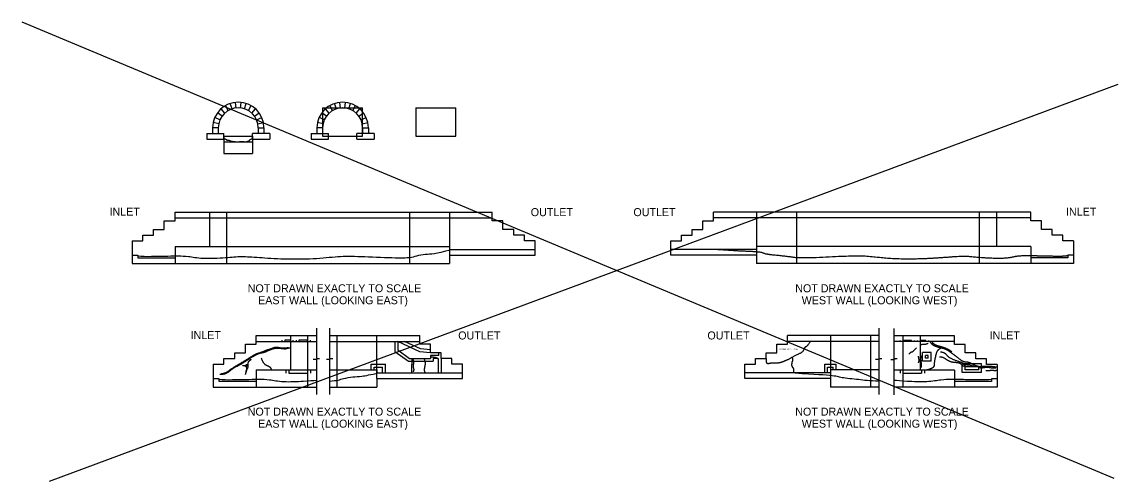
# Model space of a CAD drawing. Extents: x 21249 to 21441, y 6062 to 6293.
# Drawn here: x 21249.2 to 21441, y 6212.1 to 6292.5 of the extents above; entities that cross this region are included whole.
import ezdxf

# ---------------------------------------------------------------- set-up
doc = ezdxf.new("R2010")
doc.units = 0
for name, color, linetype in [('BR_P_Slab_Hidden', 7, 'Continuous'), ('BR_P_Slab_Object', 7, 'Continuous'), ('DR_X_Culvert', 7, 'Continuous'), ('SC_Scratch1', 7, 'Continuous'), ('SC_Scratch2', 7, 'Continuous'), ('SH_Text', 7, 'Continuous'), ('XS_X_Ground_Line', 7, 'Continuous')]:
    doc.layers.add(name, color=color, linetype=linetype)

msp = doc.modelspace()

# ---------------------------------------------------------------- linework, layer by layer
at = {"layer": 'BR_P_Slab_Hidden'}
msp.add_line((21284.56, 6271.49), (21289.56, 6271.49), dxfattribs=at)
at = {"layer": 'BR_P_Slab_Object'}
for p, q in [((21284.56, 6272.49), (21289.56, 6272.49)), ((21284.56, 6272.49), (21284.56, 6269.49)), ((21289.56, 6272.49), (21289.56, 6269.49)), ((21284.56, 6269.49), (21289.56, 6269.49))]:
    msp.add_line(p, q, dxfattribs=at)
at = {"layer": 'DR_X_Culvert'}
for p, q in [((21285.97, 6277.28), (21285.66, 6278.23)), ((21286.69, 6277.44), (21286.58, 6278.43)), ((21287.43, 6277.44), (21287.54, 6278.43)), ((21288.15, 6277.28), (21288.46, 6278.23)), ((21304.23, 6277.28), (21303.92, 6278.23)), ((21304.95, 6277.44), (21304.84, 6278.43)), ((21305.7, 6277.44), (21305.8, 6278.43)), ((21306.41, 6277.28), (21306.72, 6278.23)), ((21284.22, 6276.01), (21283.41, 6276.59)), ((21284.71, 6276.55), (21284.04, 6277.3)), ((21285.3, 6276.99), (21284.8, 6277.85)), ((21288.82, 6276.99), (21289.32, 6277.85)), ((21289.41, 6276.55), (21290.08, 6277.3)), ((21289.9, 6276.01), (21290.71, 6276.59)), ((21302.48, 6276.01), (21301.67, 6276.59)), ((21301.82, 6277.49), (21308.82, 6277.49)), ((21301.82, 6277.49), (21301.82, 6272.49)), ((21302.97, 6276.55), (21302.3, 6277.3)), ((21303.56, 6276.99), (21303.06, 6277.85)), ((21307.08, 6276.99), (21307.58, 6277.85)), ((21307.67, 6276.55), (21308.34, 6277.3)), ((21308.16, 6276.01), (21308.97, 6276.59)), ((21308.82, 6272.49), (21308.82, 6277.49)), ((21318.12, 6277.49), (21318.12, 6272.49)), ((21318.12, 6277.49), (21325.12, 6277.49)), ((21325.12, 6272.49), (21325.12, 6277.49)), ((21283.63, 6274.68), (21282.66, 6274.88)), ((21283.86, 6275.37), (21282.94, 6275.78)), ((21290.26, 6275.37), (21291.18, 6275.78)), ((21290.49, 6274.68), (21291.46, 6274.88)), ((21301.9, 6274.68), (21300.92, 6274.88)), ((21302.12, 6275.37), (21301.21, 6275.78)), ((21308.52, 6275.37), (21309.44, 6275.78)), ((21308.75, 6274.68), (21309.72, 6274.88)), ((21281.56, 6272.99), (21284.56, 6272.99)), ((21281.56, 6272.99), (21281.56, 6271.99)), ((21283.56, 6273.99), (21282.56, 6273.99)), ((21282.56, 6273.99), (21282.56, 6272.99)), ((21283.56, 6273.99), (21283.56, 6272.99)), ((21284.56, 6271.99), (21284.56, 6272.99)), ((21292.56, 6272.99), (21289.56, 6272.99)), ((21289.56, 6271.99), (21289.56, 6272.99)), ((21290.56, 6273.99), (21290.56, 6272.99)), ((21290.56, 6273.99), (21291.56, 6273.99)), ((21291.56, 6273.99), (21291.56, 6272.99)), ((21292.56, 6272.99), (21292.56, 6271.99)), ((21299.82, 6272.99), (21302.82, 6272.99)), ((21299.82, 6272.99), (21299.82, 6271.99)), ((21301.82, 6273.99), (21300.82, 6273.99)), ((21300.82, 6273.99), (21300.82, 6272.99)), ((21301.82, 6273.99), (21301.82, 6272.99)), ((21301.82, 6272.49), (21308.82, 6272.49)), ((21302.82, 6271.99), (21302.82, 6272.99)), ((21310.82, 6272.99), (21307.82, 6272.99)), ((21307.82, 6271.99), (21307.82, 6272.99)), ((21308.82, 6273.99), (21308.82, 6272.99)), ((21308.82, 6273.99), (21309.82, 6273.99)), ((21309.82, 6273.99), (21309.82, 6272.99)), ((21310.82, 6272.99), (21310.82, 6271.99)), ((21318.12, 6272.49), (21325.12, 6272.49)), ((21281.56, 6271.99), (21284.56, 6271.99)), ((21289.56, 6271.99), (21292.56, 6271.99)), ((21299.82, 6271.99), (21302.82, 6271.99)), ((21307.82, 6271.99), (21310.82, 6271.99)), ((21276, 6259.19), (21331.5, 6259.19)), ((21276, 6257.69), (21276, 6259.19)), ((21282, 6259.19), (21282, 6253.19)), ((21285, 6259.19), (21285, 6250.19)), ((21285, 6259.19), (21285, 6250.19)), ((21317, 6259.19), (21317, 6250.19)), ((21324, 6259.19), (21324, 6250.19)), ((21324, 6259.19), (21324, 6251.69)), ((21331.5, 6257.69), (21331.5, 6259.19)), ((21425.73, 6259.19), (21370.23, 6259.19)), ((21370.23, 6257.69), (21370.23, 6259.19)), ((21377.73, 6259.19), (21377.73, 6251.69)), ((21384.73, 6259.19), (21384.73, 6250.19)), ((21416.73, 6259.19), (21416.73, 6250.19)), ((21419.73, 6259.19), (21419.73, 6253.19)), ((21425.73, 6257.69), (21425.73, 6259.19)), ((21274.12, 6256.19), (21274.12, 6257.69)), ((21274.12, 6257.69), (21276, 6257.69)), ((21276, 6258.19), (21331.5, 6258.19)), ((21333.37, 6257.69), (21331.5, 6257.69)), ((21333.37, 6256.19), (21333.37, 6257.69)), ((21368.36, 6256.19), (21368.36, 6257.69)), ((21368.36, 6257.69), (21370.23, 6257.69)), ((21425.73, 6258.19), (21370.23, 6258.19)), ((21427.61, 6257.69), (21425.73, 6257.69)), ((21427.61, 6256.19), (21427.61, 6257.69)), ((21270.37, 6254.19), (21270.37, 6255.19)), ((21270.37, 6255.19), (21272.25, 6255.19)), ((21272.25, 6255.19), (21272.25, 6256.19)), ((21272.25, 6256.19), (21274.12, 6256.19)), ((21335.25, 6256.19), (21333.37, 6256.19)), ((21335.25, 6255.19), (21335.25, 6256.19)), ((21337.12, 6255.19), (21335.25, 6255.19)), ((21337.12, 6254.19), (21337.12, 6255.19)), ((21364.61, 6254.19), (21364.61, 6255.19)), ((21364.61, 6255.19), (21366.48, 6255.19)), ((21366.48, 6255.19), (21366.48, 6256.19)), ((21366.48, 6256.19), (21368.36, 6256.19)), ((21429.48, 6256.19), (21427.61, 6256.19)), ((21429.48, 6255.19), (21429.48, 6256.19)), ((21431.36, 6255.19), (21429.48, 6255.19)), ((21431.36, 6254.19), (21431.36, 6255.19)), ((21268.5, 6254.19), (21268.5, 6250.19)), ((21268.5, 6254.19), (21270.37, 6254.19)), ((21276, 6253.19), (21324, 6253.19)), ((21276, 6253.19), (21276, 6250.19)), ((21324, 6253.19), (21324, 6252.69)), ((21339, 6254.19), (21337.12, 6254.19)), ((21339, 6251.69), (21339, 6254.19)), ((21362.73, 6251.69), (21362.73, 6254.19)), ((21362.73, 6254.19), (21364.61, 6254.19)), ((21425.73, 6253.19), (21377.73, 6253.19)), ((21377.73, 6253.19), (21377.73, 6252.69)), ((21425.73, 6253.19), (21425.73, 6250.19)), ((21433.23, 6254.19), (21431.36, 6254.19)), ((21433.23, 6254.19), (21433.23, 6250.19)), ((21268.5, 6251.69), (21269.5, 6251.69)), ((21269.5, 6251.69), (21269.5, 6251.19)), ((21269.5, 6251.19), (21276, 6251.19)), ((21324, 6252.69), (21339, 6252.69)), ((21324, 6251.69), (21339, 6251.69)), ((21324, 6251.69), (21324, 6250.19)), ((21377.73, 6252.69), (21362.73, 6252.69)), ((21377.73, 6251.69), (21362.73, 6251.69)), ((21377.73, 6251.69), (21377.73, 6250.19)), ((21432.23, 6251.19), (21425.73, 6251.19)), ((21433.23, 6251.69), (21432.23, 6251.69)), ((21432.23, 6251.69), (21432.23, 6251.19)), ((21268.5, 6250.19), (21324, 6250.19)), ((21433.23, 6250.19), (21377.73, 6250.19)), ((21288.31, 6234.59), (21288.31, 6236.09)), ((21288.31, 6236.09), (21290.18, 6236.09)), ((21290.18, 6237.59), (21300.72, 6237.59)), ((21290.18, 6236.09), (21290.18, 6237.59)), ((21290.18, 6236.59), (21300.72, 6236.59)), ((21296.18, 6237.59), (21296.18, 6231.59)), ((21299.18, 6237.59), (21299.18, 6228.59)), ((21303.05, 6237.59), (21318.81, 6237.59)), ((21303.05, 6236.59), (21318.81, 6236.59)), ((21304.31, 6237.59), (21304.31, 6228.59)), ((21311.31, 6230.09), (21311.31, 6237.59)), ((21318.81, 6236.09), (21318.81, 6237.59)), ((21320.68, 6236.09), (21318.81, 6236.09)), ((21320.68, 6234.59), (21320.68, 6236.09)), ((21381.31, 6234.59), (21381.31, 6236.09)), ((21381.31, 6236.09), (21383.18, 6236.09)), ((21383.18, 6236.09), (21383.18, 6237.59)), ((21399.13, 6237.59), (21383.18, 6237.59)), ((21399.13, 6236.59), (21383.18, 6236.59)), ((21390.68, 6237.59), (21390.68, 6230.09)), ((21397.68, 6237.59), (21397.68, 6228.59)), ((21412.37, 6237.55), (21401.79, 6237.55)), ((21412.37, 6236.55), (21401.79, 6236.55)), ((21403.37, 6237.55), (21403.37, 6228.55)), ((21406.37, 6237.55), (21406.37, 6231.55)), ((21412.37, 6236.05), (21412.37, 6237.55)), ((21414.24, 6236.05), (21412.37, 6236.05)), ((21414.24, 6234.55), (21414.24, 6236.05)), ((21286.43, 6233.59), (21286.43, 6234.59)), ((21286.43, 6234.59), (21288.31, 6234.59)), ((21322.56, 6234.59), (21320.68, 6234.59)), ((21322.56, 6233.59), (21322.56, 6234.59)), ((21379.43, 6233.59), (21379.43, 6234.59)), ((21379.43, 6234.59), (21381.31, 6234.59)), ((21416.12, 6234.55), (21414.24, 6234.55)), ((21416.12, 6233.55), (21416.12, 6234.55)), ((21282.68, 6232.59), (21282.68, 6228.59)), ((21282.68, 6232.59), (21284.56, 6232.59)), ((21284.56, 6232.59), (21284.56, 6233.59)), ((21284.56, 6233.59), (21286.43, 6233.59)), ((21324.43, 6233.59), (21322.56, 6233.59)), ((21324.43, 6232.59), (21324.43, 6233.59)), ((21326.31, 6232.59), (21324.43, 6232.59)), ((21326.31, 6230.09), (21326.31, 6232.59)), ((21375.68, 6230.09), (21375.68, 6232.59)), ((21375.68, 6232.59), (21377.56, 6232.59)), ((21377.56, 6232.59), (21377.56, 6233.59)), ((21377.56, 6233.59), (21379.43, 6233.59)), ((21417.99, 6233.55), (21416.12, 6233.55)), ((21417.99, 6232.55), (21417.99, 6233.55)), ((21419.87, 6232.55), (21417.99, 6232.55)), ((21419.87, 6232.55), (21419.87, 6228.55)), ((21282.68, 6230.09), (21283.68, 6230.09)), ((21283.68, 6230.09), (21283.68, 6229.6)), ((21290.18, 6231.59), (21300.72, 6231.59)), ((21290.18, 6231.59), (21290.18, 6228.59)), ((21303.05, 6231.59), (21311.31, 6231.59)), ((21311.31, 6231.59), (21311.31, 6231.09)), ((21311.31, 6231.09), (21326.31, 6231.09)), ((21311.31, 6230.09), (21326.31, 6230.09)), ((21311.31, 6230.09), (21311.31, 6228.59)), ((21390.68, 6231.09), (21375.68, 6231.09)), ((21390.68, 6230.09), (21375.68, 6230.09)), ((21390.68, 6231.59), (21390.68, 6231.09)), ((21399.13, 6231.59), (21390.68, 6231.59)), ((21390.68, 6230.09), (21390.68, 6228.59)), ((21412.37, 6231.55), (21401.79, 6231.55)), ((21412.37, 6231.55), (21412.37, 6228.55)), ((21282.68, 6228.59), (21300.72, 6228.59)), ((21283.68, 6229.59), (21290.18, 6229.59)), ((21303.05, 6228.59), (21311.31, 6228.59)), ((21399.13, 6228.59), (21390.68, 6228.59)), ((21419.87, 6228.55), (21401.79, 6228.55)), ((21418.87, 6229.55), (21412.37, 6229.55)), ((21419.87, 6230.05), (21418.87, 6230.05)), ((21418.87, 6230.05), (21418.87, 6229.56))]:
    msp.add_line(p, q, dxfattribs=at)
for centre in [(21288.53, 6232.39), (21413.97, 6232.35)]:
    msp.add_circle(centre, 0.167, dxfattribs=at)
for centre, radius in [((21287.06, 6273.96), 4.5), ((21305.32, 6273.96), 4.5), ((21287.06, 6273.96), 3.5), ((21305.32, 6273.96), 3.5)]:
    msp.add_arc(centre, radius, 0.4626, 179.5374, dxfattribs=at)
for points in [[(21406.37, 6236.03), (21407.01, 6236.1), (21407.32, 6236.1), (21407.77, 6236.26), (21407.77, 6236.26)], [(21419.74, 6232.05), (21418.52, 6232.25), (21417.34, 6232.16), (21416.62, 6232.13), (21415.74, 6232.47), (21414.91, 6232.94), (21413.99, 6232.94), (21412.94, 6233.73), (21412.08, 6234.41), (21411.15, 6235.07), (21410.23, 6235.42), (21409.32, 6235.58), (21408.4, 6236.02), (21408.14, 6236.55)], [(21411.91, 6234.75), (21411.36, 6235.17), (21410.18, 6235.61), (21409.25, 6235.83), (21408.67, 6236.16), (21408.53, 6236.42)], [(21283.85, 6230.83), (21284.57, 6230.83), (21285.38, 6231.23), (21286.12, 6231.87), (21287.43, 6232.54), (21288.34, 6233.13), (21289.61, 6233.92), (21290.54, 6234.49), (21291.67, 6234.66), (21292.73, 6235.2), (21293.89, 6235.48), (21295.29, 6235.24), (21295.91, 6235.49), (21296.18, 6235.42)], [(21284.09, 6230.92), (21284.77, 6231.06), (21285.17, 6231.27), (21285.97, 6231.85), (21286.87, 6232.42), (21288.11, 6233.14), (21289.25, 6233.85), (21290.13, 6234.4), (21290.87, 6234.6), (21292.07, 6235.1), (21292.76, 6235.29), (21293.35, 6235.56), (21294.06, 6235.56), (21294.56, 6235.43), (21295.4, 6235.43), (21295.65, 6235.5), (21295.82, 6235.53)], [(21405.7, 6235.44), (21405.33, 6235.04), (21404.98, 6234.67), (21404.71, 6234.67), (21404.41, 6234.36)], [(21406.02, 6234.02), (21406.15, 6233.41), (21406.15, 6233.09), (21406.03, 6232.83)], [(21406.59, 6232.01), (21406.59, 6232.51), (21406.59, 6233.01), (21406.48, 6233.52), (21406.59, 6234.03)], [(21410.07, 6235.43), (21409.49, 6235.1), (21409.21, 6234.67), (21408.85, 6233.01), (21408.85, 6232.15), (21408.4, 6231.84), (21407.62, 6231.55), (21407.19, 6231.55)], [(21415.96, 6232.13), (21415.13, 6232.44), (21414.54, 6232.44), (21414.1, 6232.58), (21413.69, 6232.86), (21412.44, 6233.25), (21411.34, 6233.8), (21410.82, 6234.48), (21410.13, 6234.7), (21409.93, 6234.7)], [(21287.82, 6232.33), (21288.21, 6232.4), (21288.44, 6232.13), (21288.55, 6231.69), (21288.4, 6231.18), (21288.27, 6230.78)], [(21288.43, 6231.3), (21288.49, 6231.6), (21288.8, 6231.98), (21288.8, 6232.48), (21288.8, 6232.93), (21289.04, 6233.25), (21289.33, 6233.45)], [(21291.06, 6233.66), (21291.37, 6232.92), (21291.8, 6232.47), (21292.43, 6232.24), (21292.75, 6231.95), (21292.89, 6231.59)], [(21317.45, 6233.59), (21317.45, 6232.76), (21317.33, 6232.11), (21317.41, 6231.63), (21317.37, 6231.09)], [(21317.58, 6233.59), (21317.76, 6232.77), (21317.66, 6232.48), (21317.66, 6232.05), (21317.81, 6231.56), (21317.66, 6231.27)], [(21319.56, 6233.59), (21319.82, 6232.9), (21319.67, 6232.15), (21319.56, 6231.43), (21319.74, 6231.09)], [(21320.68, 6233.86), (21321.42, 6233.86), (21321.89, 6233.65), (21322.11, 6233.52)], [(21383.95, 6233.8), (21384.14, 6233.35), (21383.89, 6232.88), (21383.89, 6232.15), (21384.32, 6231.77), (21384.2, 6231.09)], [(21413.84, 6232.45), (21413.52, 6232.63), (21413, 6232.85), (21412.67, 6232.85), (21411.72, 6232.97), (21411.08, 6233.33), (21410.29, 6233.84), (21409.79, 6233.84)], [(21414.48, 6232.13), (21414.29, 6232.23), (21414.23, 6232.23), (21414.13, 6232.3)], [(21419.62, 6231.88), (21418.93, 6231.88), (21418.17, 6232.07), (21417.64, 6231.97), (21416.97, 6231.88), (21416.62, 6232.02)], [(21417.86, 6231.46), (21418.44, 6231.46), (21418.84, 6231.58), (21419.54, 6231.47), (21419.74, 6231.54)]]:
    msp.add_open_spline(points, degree=2, dxfattribs=at)
at = {"layer": 'SC_Scratch1'}
for p, q in [((21249.2, 6292.51), (21440.26, 6212.63)), ((21254, 6212.12), (21441.01, 6281.64)), ((21296.18, 6236.79), (21295.18, 6236.79)), ((21295.18, 6236.79), (21295.18, 6236.59)), ((21296.18, 6236.59), (21296.18, 6236.79)), ((21299.18, 6236.79), (21297.68, 6236.79)), ((21297.68, 6236.79), (21297.68, 6236.59)), ((21299.18, 6236.59), (21299.18, 6236.79)), ((21314.98, 6236.59), (21314.98, 6235.09)), ((21318.81, 6234.76), (21314.98, 6236.59)), ((21404.87, 6236.75), (21403.37, 6236.75)), ((21403.37, 6236.75), (21403.37, 6236.55)), ((21404.87, 6236.55), (21404.87, 6236.75)), ((21407.37, 6236.75), (21406.37, 6236.75)), ((21406.37, 6236.75), (21406.37, 6236.55)), ((21407.37, 6236.55), (21407.37, 6236.75)), ((21314.98, 6235.09), (21317.02, 6233.59)), ((21320.68, 6234.59), (21318.81, 6234.76)), ((21322.18, 6234.09), (21320.68, 6234.09)), ((21320.68, 6234.09), (21320.68, 6233.59)), ((21322.18, 6234.09), (21322.18, 6234.59)), ((21407.29, 6233.64), (21407.29, 6234.14)), ((21407.79, 6234.14), (21407.29, 6234.14)), ((21407.79, 6233.64), (21407.79, 6234.14)), ((21310.81, 6232.09), (21312.31, 6232.09)), ((21310.81, 6231.59), (21310.81, 6232.09)), ((21312.31, 6231.09), (21312.31, 6232.09)), ((21317.02, 6233.59), (21320.68, 6233.59)), ((21322.06, 6233.59), (21322.06, 6231.09)), ((21322.56, 6233.59), (21322.56, 6231.09)), ((21390.18, 6232.09), (21391.18, 6232.09)), ((21390.18, 6231.09), (21390.18, 6232.09)), ((21391.18, 6231.59), (21391.18, 6232.09)), ((21407.79, 6233.64), (21407.29, 6233.64)), ((21416.62, 6232.13), (21414.24, 6232.13)), ((21414.24, 6231.63), (21414.24, 6232.13)), ((21416.62, 6231.63), (21416.62, 6232.13)), ((21295.91, 6231.59), (21295.91, 6231.03)), ((21295.91, 6231.03), (21299.18, 6231.03)), ((21299.18, 6231.59), (21299.18, 6231.03)), ((21403.37, 6231.55), (21403.37, 6230.99)), ((21403.37, 6230.99), (21406.64, 6230.99)), ((21406.64, 6231.55), (21406.64, 6230.99)), ((21416.62, 6231.63), (21414.24, 6231.63))]:
    msp.add_line(p, q, dxfattribs=at)
msp.add_open_spline([(21379.43, 6233.59), (21379.43, 6233.14), (21379.43, 6232.92), (21379.56, 6232.73), (21379.97, 6232.73), (21380.46, 6232.86), (21381.31, 6232.8), (21382.11, 6232.94), (21382.99, 6233.29), (21383.81, 6233.7), (21384.5, 6234.16), (21385.85, 6234.69), (21386.25, 6235.62), (21386.75, 6235.87), (21387.18, 6236.59)], degree=2, dxfattribs=at)
at = {"layer": 'SC_Scratch2'}
for p, q in [((21294.68, 6236.79), (21294.68, 6236.59)), ((21296.68, 6236.59), (21296.68, 6236.79)), ((21297.18, 6236.79), (21297.18, 6236.59)), ((21299.68, 6236.59), (21299.68, 6236.79)), ((21314.48, 6236.59), (21314.48, 6234.84)), ((21318.94, 6235.25), (21316.13, 6236.59)), ((21402.87, 6236.75), (21402.87, 6236.55)), ((21405.37, 6236.55), (21405.37, 6236.75)), ((21405.87, 6236.75), (21405.87, 6236.55)), ((21407.87, 6236.55), (21407.87, 6236.75)), ((21314.48, 6234.84), (21316.85, 6233.09)), ((21320.68, 6235.1), (21318.94, 6235.25)), ((21408.29, 6234.64), (21406.79, 6234.64)), ((21406.79, 6233.14), (21406.79, 6234.64)), ((21408.29, 6233.14), (21408.29, 6234.64)), ((21310.31, 6231.59), (21310.31, 6232.59)), ((21310.31, 6232.59), (21312.81, 6232.59)), ((21312.81, 6231.09), (21312.81, 6232.59)), ((21316.85, 6233.09), (21321.18, 6233.09)), ((21322.06, 6233.59), (21321.18, 6233.59)), ((21321.18, 6233.59), (21321.18, 6233.09)), ((21389.68, 6232.59), (21391.68, 6232.59)), ((21389.68, 6231.09), (21389.68, 6232.59)), ((21391.68, 6231.59), (21391.68, 6232.59)), ((21408.29, 6233.14), (21406.79, 6233.14)), ((21417.12, 6232.63), (21413.74, 6232.63)), ((21413.74, 6231.13), (21413.74, 6232.63)), ((21417.12, 6231.13), (21417.12, 6232.63)), ((21295.41, 6231.59), (21295.41, 6231.03)), ((21299.68, 6231.59), (21299.68, 6231.03)), ((21402.87, 6231.55), (21402.87, 6230.99)), ((21407.14, 6231.55), (21407.14, 6230.99)), ((21417.12, 6231.13), (21413.74, 6231.13))]:
    msp.add_line(p, q, dxfattribs=at)
at = {"layer": 'SH_Text'}
for p, q in [((21300.72, 6238.9), (21300.72, 6233.67)), ((21303.05, 6238.9), (21303.05, 6233.67)), ((21399.13, 6238.9), (21399.13, 6233.67)), ((21401.79, 6238.86), (21401.79, 6233.63)), ((21300.17, 6233.49), (21301.27, 6233.61)), ((21300.17, 6233.49), (21300.72, 6233.42)), ((21300.72, 6233.67), (21301.27, 6233.61)), ((21300.72, 6233.42), (21300.72, 6227.29)), ((21302.51, 6233.49), (21303.6, 6233.61)), ((21302.51, 6233.49), (21303.05, 6233.42)), ((21303.05, 6233.67), (21303.6, 6233.61)), ((21303.05, 6233.42), (21303.05, 6227.29)), ((21398.58, 6233.49), (21399.68, 6233.61)), ((21398.58, 6233.49), (21399.13, 6233.42)), ((21399.13, 6233.67), (21399.68, 6233.61)), ((21399.13, 6233.42), (21399.13, 6227.29)), ((21401.24, 6233.44), (21402.34, 6233.57)), ((21401.24, 6233.44), (21401.79, 6233.38)), ((21401.79, 6233.63), (21402.34, 6233.57)), ((21401.79, 6233.38), (21401.79, 6227.25))]:
    msp.add_line(p, q, dxfattribs=at)
at = {"layer": 'XS_X_Ground_Line'}
for points, degree in [([(21284.56, 6272.07), (21284.91, 6272.02), (21285.09, 6271.75), (21285.48, 6271.84), (21285.75, 6271.63), (21286.54, 6271.54), (21287.07, 6271.49), (21287.7, 6271.64), (21288.23, 6271.49), (21288.95, 6271.66), (21289.19, 6272.02), (21289.56, 6272.06)], 2), ([(21269.5, 6251.56), (21270.2, 6251.46), (21271.7, 6251.46), (21275.03, 6251.54), (21276.53, 6251.54), (21278.27, 6251.54), (21280.53, 6251.02), (21285.2, 6251.24), (21287.49, 6251.52), (21290.53, 6251.29), (21294.93, 6250.99), (21300.33, 6250.99), (21304.66, 6251.51), (21308.02, 6251.51), (21314.53, 6251.17), (21316.53, 6251.24), (21317, 6251.27)], 3), ([(21317, 6251.27), (21317.58, 6251.31), (21318.17, 6251.6), (21319.82, 6251.89), (21321.19, 6251.9), (21322.86, 6252.25), (21324.44, 6252.69)], 3), ([(21432.23, 6251.56), (21431.53, 6251.46), (21430.03, 6251.46), (21426.7, 6251.54), (21425.2, 6251.54), (21423.46, 6251.54), (21421.19, 6251.02), (21416.53, 6251.24), (21414.24, 6251.52), (21411.2, 6251.29), (21406.8, 6250.99), (21401.39, 6250.99), (21397.07, 6251.51), (21393.71, 6251.51), (21385.44, 6251.09), (21382.84, 6251.49), (21379.34, 6251.81), (21378.6, 6252.23), (21373.99, 6252.42), (21370.23, 6252.69)], 2), ([(21303.05, 6229.63), (21304.31, 6229.71), (21305.48, 6230.11), (21307.14, 6230.4), (21308.51, 6230.41), (21310.18, 6230.76), (21311.64, 6231.09)], 3), ([(21399.13, 6229.63), (21397.46, 6229.63), (21395.74, 6229.9), (21392.29, 6230.21), (21391.55, 6230.63), (21386.94, 6230.83), (21383.18, 6231.09)], 3), ([(21283.68, 6229.96), (21284.39, 6229.87), (21285.89, 6229.87), (21289.22, 6229.95), (21290.72, 6229.95), (21292.45, 6229.95), (21294.72, 6229.43), (21298.74, 6229.62), (21300.21, 6229.76), (21300.72, 6229.79)], 3), ([(21418.87, 6229.92), (21418.16, 6229.83), (21416.66, 6229.83), (21413.33, 6229.9), (21411.83, 6229.9), (21410.1, 6229.9), (21407.83, 6229.39), (21403.79, 6229.58), (21402.31, 6229.72), (21401.79, 6229.76)], 3)]:
    msp.add_open_spline(points, degree=degree, dxfattribs=at)

# ---------------------------------------------------------------- texts
at = {"layer": 'SC_Scratch1'}
for s, height, p in [('INLET', 1.4, (21264.53, 6258.59)), ('OUTLET', 1.4, (21338.24, 6258.51)), ('OUTLET', 1.4, (21356.2, 6258.51)), ('INLET', 1.4, (21431.9, 6258.59)), ('NOT DRAWN EXACTLY TO SCALE', 1.4, (21288.71, 6245.18)), ('NOT DRAWN EXACTLY TO SCALE', 1.4, (21384.52, 6245.18)), ('EAST WALL (LOOKING EAST)', 1.4, (21290.53, 6243.08)), ('WEST WALL (LOOKING WEST)', 1.4, (21385.65, 6243.08)), ('INLET', 1.4, (21278.72, 6236.99)), ('OUTLET', 1.4, (21325.55, 6236.92)), ('OUTLET', 1.4, (21369.15, 6236.92)), ('INLET', 1.4, (21418.53, 6236.95)), ('PATCHING - DO NOT LABEL', 0.175, (21381.73, 6235.16)), ('NOT DRAWN EXACTLY TO SCALE', 1.4, (21288.71, 6223.58)), ('NOT DRAWN EXACTLY TO SCALE', 1.4, (21384.52, 6223.58)), ('EAST WALL (LOOKING EAST)', 1.4, (21290.53, 6221.48)), ('WEST WALL (LOOKING WEST)', 1.4, (21385.65, 6221.48))]:
    msp.add_text(s, height=height, dxfattribs=at).set_placement(p)

doc.saveas('drawing.dxf')
